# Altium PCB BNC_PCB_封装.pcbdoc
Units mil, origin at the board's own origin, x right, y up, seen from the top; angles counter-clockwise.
Board outline 1592.68 x 2442.62 mil, 2 copper layers (Top Layer, Bottom Layer); 1 components, 10 nets, 4 pads, 0 vias.
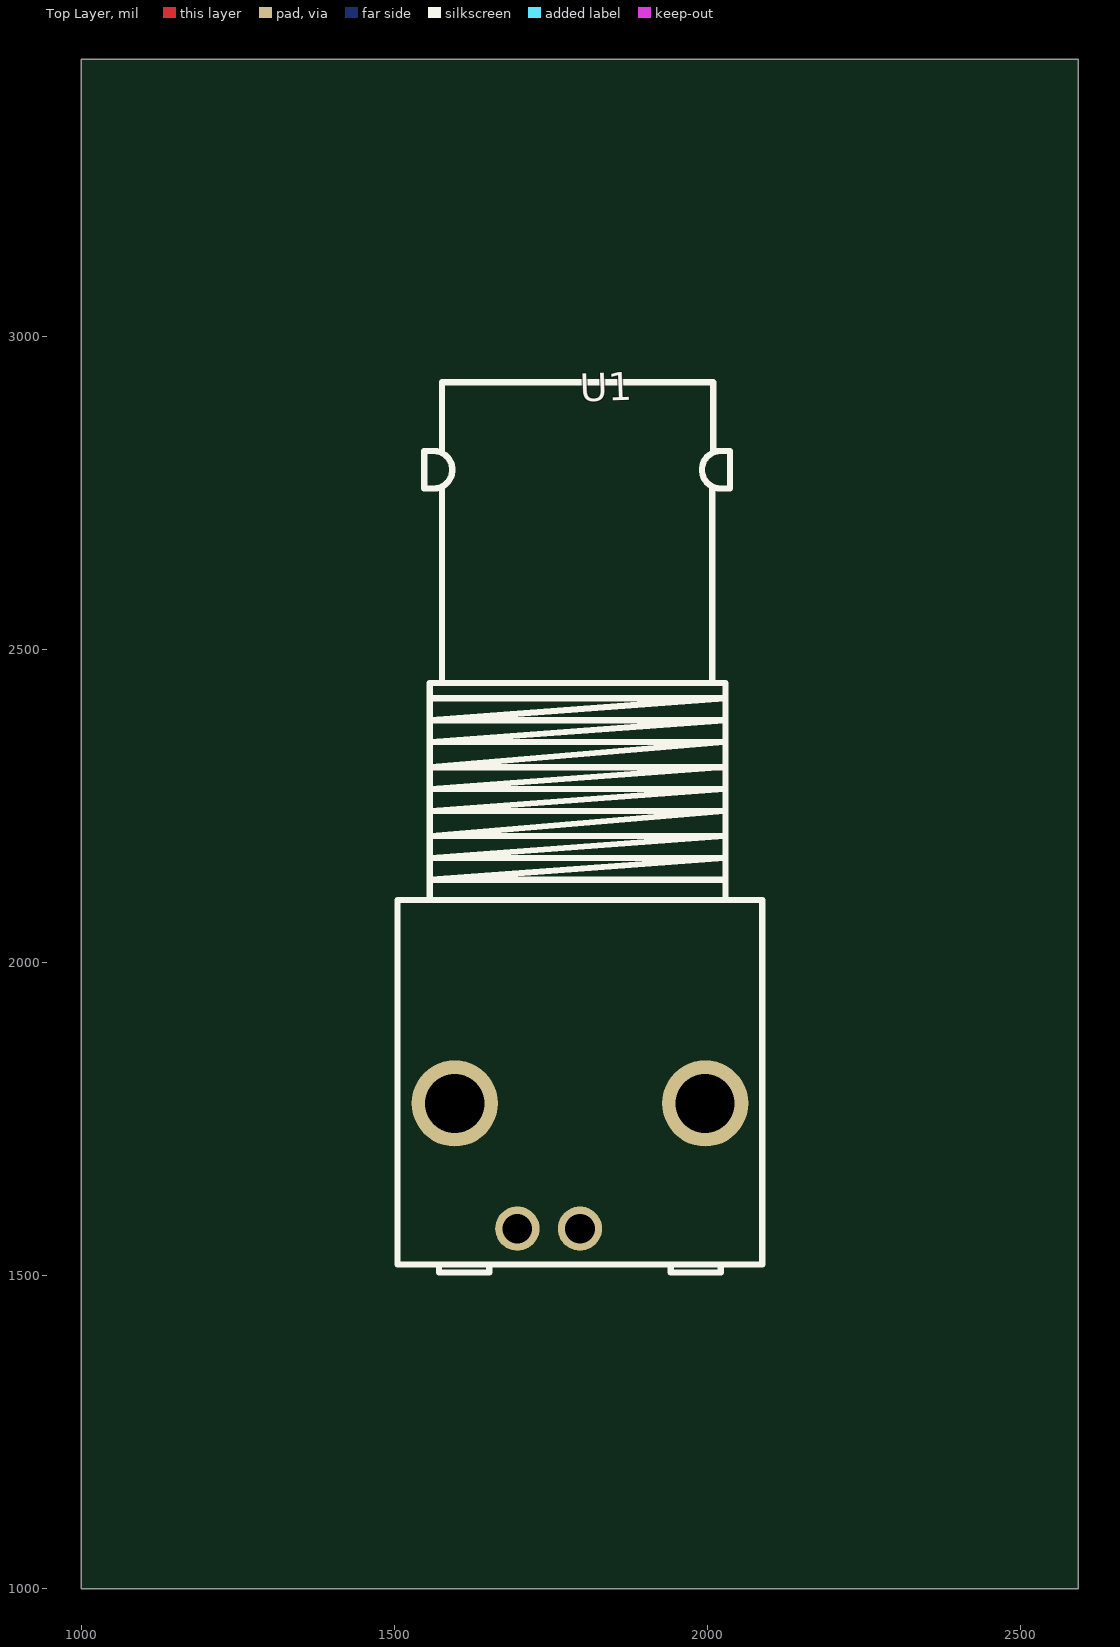
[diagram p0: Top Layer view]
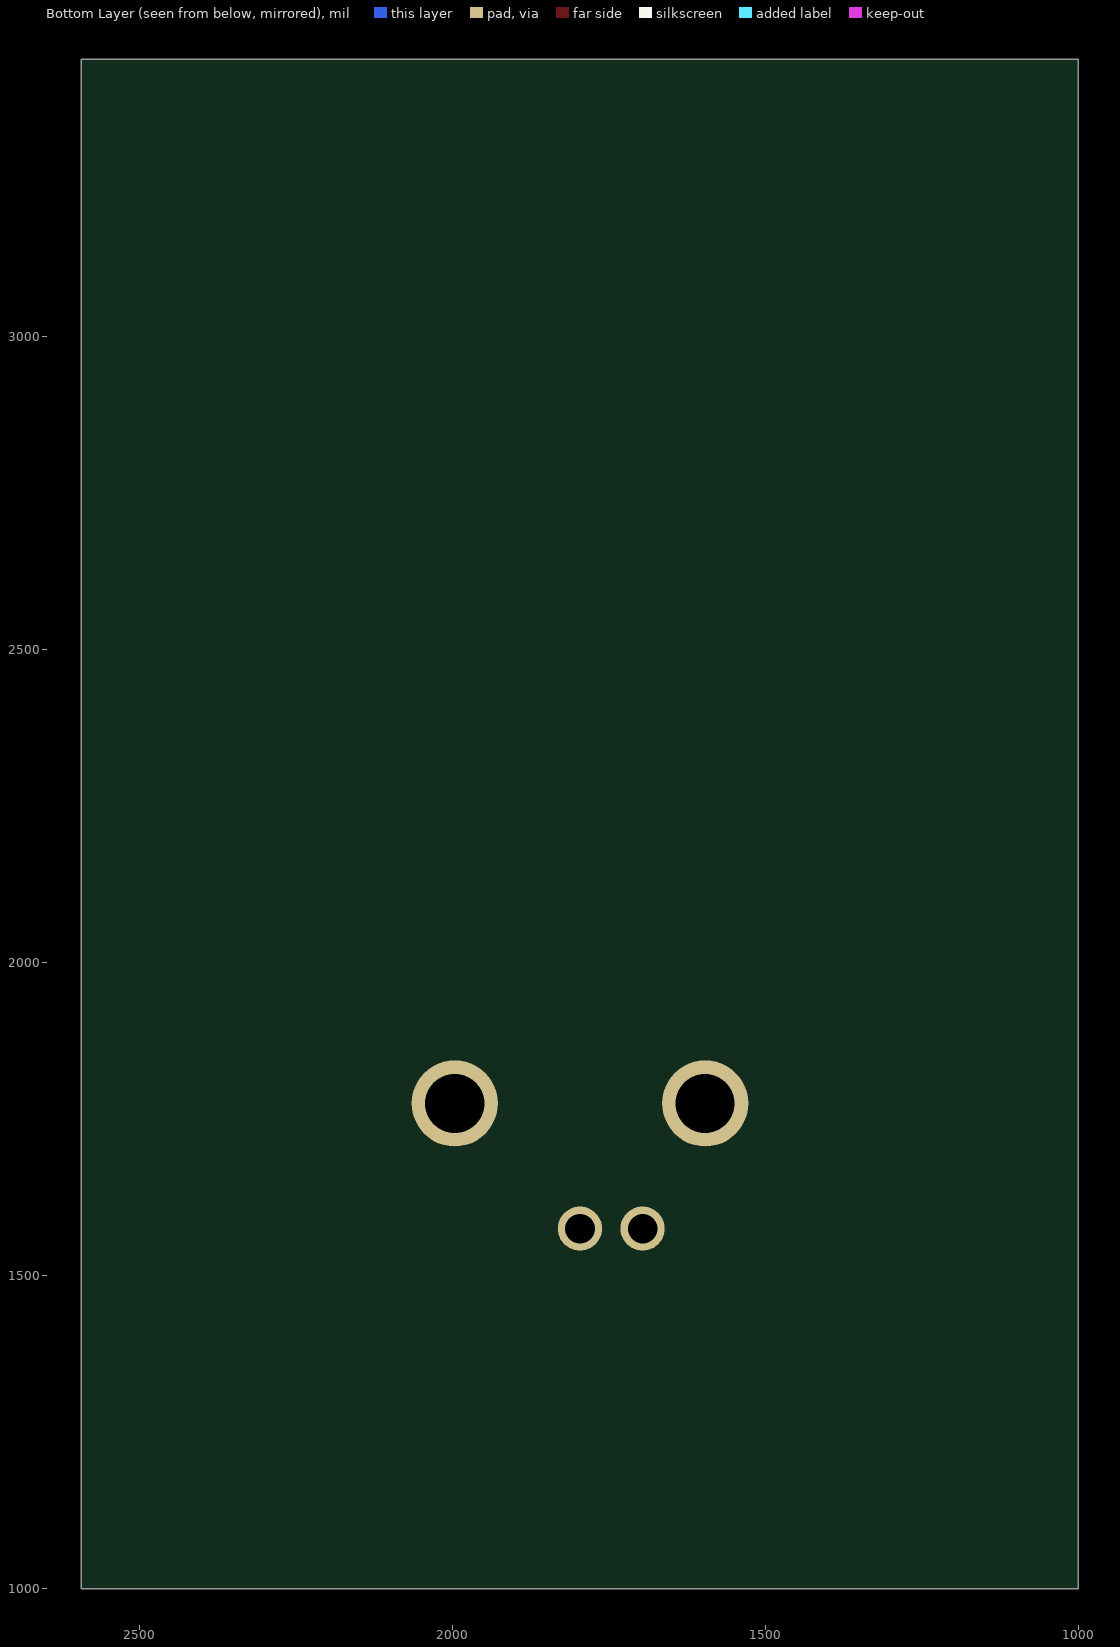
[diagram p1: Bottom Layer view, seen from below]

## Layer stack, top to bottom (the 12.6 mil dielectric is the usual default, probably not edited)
Top Layer: signal copper (thickness not stored)
Dielectric: dielectric 12.6, FR-4, Dk 4.8
Bottom Layer: signal copper (thickness not stored)

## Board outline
2592.68,1000 1000,1000 1000,3442.62 2592.68,3442.62

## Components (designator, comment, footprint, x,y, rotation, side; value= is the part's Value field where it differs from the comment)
U1 "5227661-1" 5227661-1 1796.34,1675 r0 top

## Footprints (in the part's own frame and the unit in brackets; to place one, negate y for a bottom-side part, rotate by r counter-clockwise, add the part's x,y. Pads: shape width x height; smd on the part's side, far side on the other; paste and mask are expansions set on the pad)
5227661-1 [mm]
  round 1.8 hole 1.2: 1(0,-2.54) 2(-2.54,-2.54)
  round 3.5 hole 2.4: 3(-5.08,2.54) 4(5.08,2.54)
  silkscreen extent -7.4,-4.32 7.4,31.81

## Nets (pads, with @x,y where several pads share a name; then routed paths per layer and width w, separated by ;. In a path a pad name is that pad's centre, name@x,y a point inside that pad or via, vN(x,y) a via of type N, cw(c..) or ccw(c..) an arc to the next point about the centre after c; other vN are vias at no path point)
S$36: 
S$38: 
S$41: 
S$43: 
S$45: 
S$50: 
S$52: 
S$60: 
S$64: 
S$66: 
pads on no net: U1.1 U1.2 U1.3 U1.4

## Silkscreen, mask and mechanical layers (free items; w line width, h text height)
Document:
  lines w0.1: 1795.34,2220.31 1797.34,2222.31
